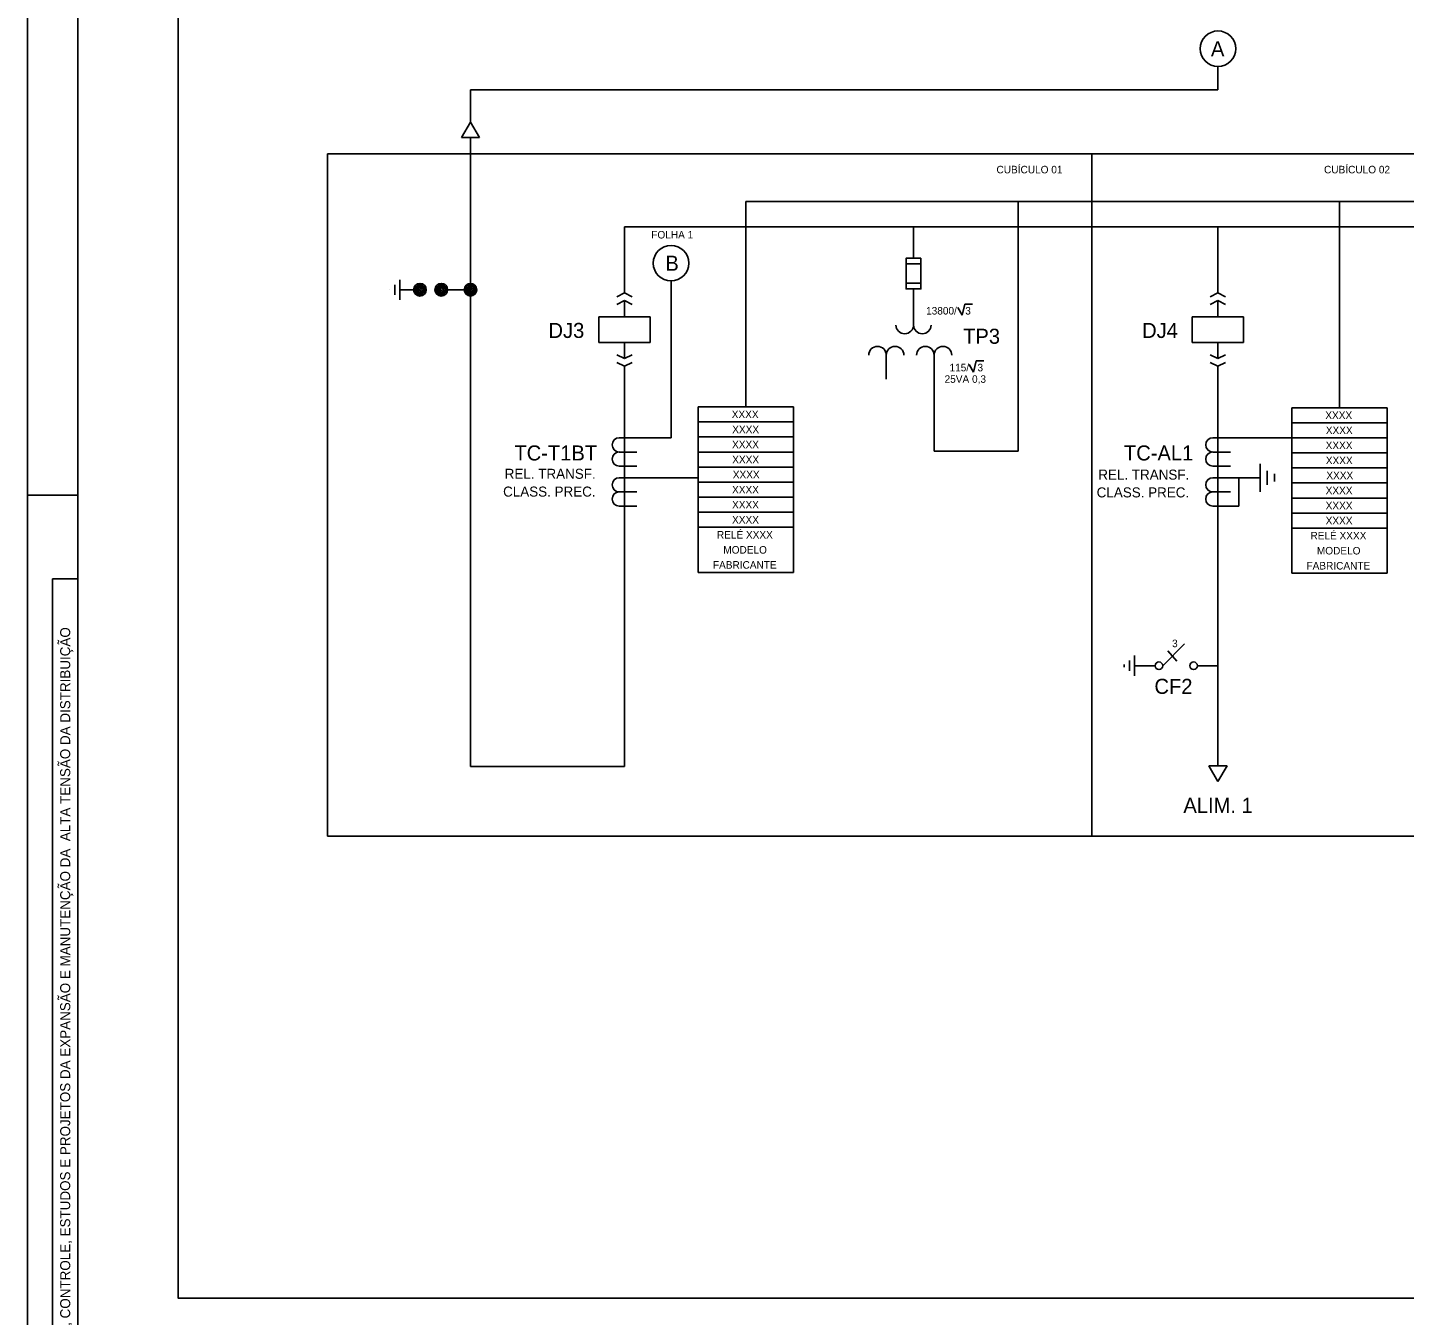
# Model space of a CAD drawing. Extents: x 563 to 1404, y 358 to 952.
# Drawn here: x 562.6 to 837, y 491.5 to 748.2 of the extents above; entities that cross this region are included whole.
import ezdxf

# ---------------------------------------------------------------- set-up
doc = ezdxf.new("R2010")
doc.units = 0
doc.layers.add('13', color=7, linetype='Continuous')
doc.layers.add('New Level (0)', color=7, linetype='Continuous')

# ---------------------------------------------------------------- blocks, each defined once
blk = doc.blocks.new('_U3')
for p, q in [((-1.47, 0.42), (-0.62, -1.12)), ((-0.62, -1.12), (-0.07, 1.12)), ((-0.07, 1.12), (1.47, 1.12))]:
    blk.add_line(p, q)

msp = doc.modelspace()

# ---------------------------------------------------------------- linework, layer by layer
for p, q in [((799.81, 740.38), (799.81, 735.75)), ((650.86, 729.31), (650.86, 735.75)), ((650.86, 735.75), (799.81, 735.75)), ((650.86, 729.31), (649.05, 726.21)), ((652.67, 726.21), (650.86, 729.31)), ((649.05, 726.21), (652.67, 726.21)), ((649.05, 726.21), (652.67, 726.21)), ((1296.89, 722.95), (622.37, 722.95)), ((622.37, 722.95), (622.37, 586.96)), ((774.67, 722.95), (774.67, 586.96)), ((774.67, 722.95), (774.67, 586.96)), ((1280.96, 713.45), (705.72, 713.45)), ((705.72, 672.55), (705.72, 713.45)), ((759.97, 663.73), (759.97, 713.45)), ((824.01, 672.38), (824.01, 713.45)), ((1256.75, 708.46), (681.52, 708.46)), ((681.52, 695.25), (681.52, 708.46)), ((739.14, 708.46), (739.14, 702.17)), ((799.81, 695.25), (799.81, 708.46)), ((799.81, 695.25), (799.81, 708.46)), ((740.6, 701.05), (737.67, 701.05)), ((636.77, 693.89), (636.77, 697.89)), ((690.82, 666.38), (690.82, 697.64)), ((740.6, 697.18), (737.67, 697.18)), ((634.77, 695.89), (634.77, 695.89)), ((635.77, 696.89), (635.77, 694.89)), ((640.77, 695.89), (636.77, 695.89)), ((640.77, 695.89), (636.77, 695.89)), ((650.86, 695.89), (646.27, 695.89)), ((739.14, 696.05), (739.14, 688.86)), ((681.52, 690.5), (681.52, 693.73)), ((681.52, 690.5), (681.52, 693.73)), ((799.81, 690.5), (799.81, 693.73)), ((799.81, 690.5), (799.81, 693.73)), ((676.4, 685.38), (676.4, 690.5)), ((676.4, 690.5), (686.64, 690.5)), ((686.64, 690.5), (686.64, 685.38)), ((794.69, 685.38), (794.69, 690.5)), ((794.69, 690.5), (804.93, 690.5)), ((804.93, 690.5), (804.93, 685.38)), ((686.64, 685.38), (676.4, 685.38)), ((681.52, 685.38), (681.52, 682.16)), ((804.93, 685.38), (794.69, 685.38)), ((799.81, 685.38), (799.81, 682.16)), ((681.52, 600.87), (681.52, 680.63)), ((733.71, 678.08), (733.71, 682.86)), ((743.25, 682.86), (743.25, 663.73)), ((799.81, 600.97), (799.81, 680.63)), ((715.21, 672.55), (696.23, 672.55)), ((696.23, 672.55), (696.23, 639.55)), ((715.21, 672.55), (715.21, 639.55)), ((833.5, 672.38), (814.52, 672.38)), ((814.52, 672.38), (814.52, 639.38)), ((833.5, 672.38), (833.5, 639.38)), ((715.21, 669.55), (696.23, 669.55)), ((833.5, 669.38), (814.52, 669.38)), ((680.5, 666.38), (684.03, 666.38)), ((690.82, 666.38), (684.03, 666.38)), ((715.21, 666.55), (696.23, 666.55)), ((798.79, 666.38), (802.32, 666.38)), ((814.52, 666.38), (802.32, 666.38)), ((833.5, 666.38), (814.52, 666.38)), ((680.5, 663.55), (684.03, 663.55)), ((715.21, 663.55), (696.23, 663.55)), ((759.97, 663.73), (743.25, 663.73)), ((798.79, 663.55), (802.32, 663.55)), ((833.5, 663.38), (814.52, 663.38)), ((680.5, 660.72), (684.03, 660.72)), ((715.21, 660.55), (696.23, 660.55)), ((798.79, 660.72), (802.32, 660.72)), ((808.19, 661.21), (808.19, 655.63)), ((809.59, 657.02), (809.59, 659.82)), ((811.07, 659.2), (811.07, 657.64)), ((833.5, 660.38), (814.52, 660.38)), ((680.5, 658.42), (684.03, 658.42)), ((696.23, 658.42), (684.03, 658.42)), ((715.21, 657.55), (696.23, 657.55)), ((798.79, 658.42), (802.32, 658.42)), ((799.81, 658.42), (808.19, 658.42)), ((833.5, 657.38), (814.52, 657.38)), ((680.5, 655.59), (684.03, 655.59)), ((715.21, 654.55), (696.23, 654.55)), ((715.21, 654.55), (696.23, 654.55)), ((798.79, 655.59), (802.32, 655.59)), ((833.5, 654.38), (814.52, 654.38)), ((833.5, 654.38), (814.52, 654.38)), ((680.5, 652.76), (684.03, 652.76)), ((715.21, 651.55), (696.23, 651.55)), ((798.79, 652.76), (804, 652.76)), ((833.5, 651.38), (814.52, 651.38)), ((715.21, 648.55), (696.23, 648.55)), ((833.5, 648.38), (814.52, 648.38)), ((715.21, 639.55), (696.23, 639.55)), ((833.5, 639.38), (814.52, 639.38)), ((783.18, 623), (783.18, 618.91)), ((793.15, 625.29), (788.81, 620.95)), ((789.8, 623.9), (791.6, 621.88)), ((781.14, 621.19), (781.14, 620.66)), ((782.15, 619.93), (782.15, 621.98)), ((787.27, 620.95), (783.18, 620.95)), ((799.81, 620.95), (795.71, 620.95)), ((801.62, 600.97), (798, 600.97)), ((798, 600.97), (799.81, 597.87)), ((801.62, 600.97), (798, 600.97)), ((799.81, 597.87), (801.62, 600.97)), ((1296.89, 586.96), (622.37, 586.96))]:
    msp.add_line(p, q)
msp.add_lwpolyline([(681.52, 600.87), (650.86, 600.87), (650.86, 726.21)])
msp.add_lwpolyline([(740.6, 702.17), (737.67, 702.17), (737.67, 696.05), (740.6, 696.05)], close=True)
for centre, radius in [((640.77, 695.89), 1.25), ((645.02, 695.89), 1.25), ((650.86, 695.89), 1.25), ((640.77, 695.89), 1), ((640.77, 695.89), 0.75), ((640.77, 695.89), 0.5), ((640.77, 695.89), 0.25), ((645.02, 695.89), 1), ((645.02, 695.89), 0.75), ((645.02, 695.89), 0.5), ((645.02, 695.89), 0.25), ((650.86, 695.89), 1), ((650.86, 695.89), 0.75), ((650.86, 695.89), 0.5), ((650.86, 695.89), 0.25), ((788.04, 620.95), 0.768), ((794.95, 620.95), 0.768)]:
    msp.add_circle(centre, radius)
for centre, radius, start, end in [((737.39, 688.86), 1.75, 180, 360), ((740.89, 688.86), 1.75, 180, 360), ((731.96, 682.86), 1.75, 0, 180), ((735.46, 682.86), 1.75, 0, 180), ((741.5, 682.86), 1.75, 0, 180), ((745, 682.86), 1.75, 0, 180), ((680.5, 664.97), 1.42, 90, 270), ((798.79, 664.97), 1.42, 90, 270), ((680.5, 662.14), 1.42, 90, 270), ((798.79, 662.14), 1.42, 90, 270), ((680.5, 657.01), 1.42, 90, 270), ((798.79, 657.01), 1.42, 90, 270), ((680.5, 654.18), 1.42, 90, 270), ((798.79, 654.18), 1.42, 90, 270)]:
    msp.add_arc(centre, radius, start, end)
at = {"layer": '13'}
for p, q in [((681.52, 695.25), (679.99, 694.49)), ((681.52, 695.25), (683.05, 694.49)), ((799.81, 695.25), (798.28, 694.49)), ((799.81, 695.25), (801.34, 694.49)), ((681.52, 693.73), (679.99, 692.97)), ((681.52, 693.73), (683.05, 692.97)), ((799.81, 693.73), (798.28, 692.97)), ((799.81, 693.73), (801.34, 692.97)), ((681.52, 682.16), (679.99, 682.92)), ((681.52, 680.63), (679.99, 681.4)), ((681.52, 682.16), (683.05, 682.92)), ((681.52, 680.63), (683.05, 681.4)), ((799.81, 682.16), (798.28, 682.92)), ((799.81, 680.63), (798.28, 681.4)), ((799.81, 682.16), (801.34, 682.92)), ((799.81, 680.63), (801.34, 681.4))]:
    msp.add_line(p, q, dxfattribs=at)
at = {"layer": 'New Level (0)'}
for p, q in [((562.58, 951.96), (562.58, 357.96)), ((562.58, 951.96), (562.58, 357.96)), ((572.58, 941.96), (572.58, 367.96)), ((572.58, 941.96), (572.58, 367.96)), ((804, 658.42), (804, 652.76)), ((562.58, 654.96), (572.58, 654.96)), ((567.58, 638.29), (572.58, 638.29)), ((567.58, 434.97), (567.58, 638.29))]:
    msp.add_line(p, q, dxfattribs=at)
msp.add_lwpolyline([(592.61, 760.21), (1379.09, 760.21), (1379.09, 494.89), (592.61, 494.89)], close=True, dxfattribs=at)
for centre in [(799.81, 743.93), (690.82, 701.18)]:
    msp.add_circle(centre, 3.54, dxfattribs=at)

# ---------------------------------------------------------------- block references
for p in [(749.45, 691.92), (751.68, 680.6)]:
    msp.add_blockref('_U3', p)

# ---------------------------------------------------------------- texts
for s, height, p in [('A', 3, (798.41, 742.43)), ('CUBÍCULO 01', 1.5, (755.67, 719.09)), ('CUBÍCULO 02', 1.5, (820.95, 719.09)), ('FOLHA 1', 1.5, (686.88, 706.11)), ('B', 3, (689.69, 699.68)), ('13800/   3', 1.5, (741.64, 690.95)), ('DJ3', 3, (666.39, 686.28)), ('DJ4', 3, (784.69, 686.28)), ('TP3', 3, (749.02, 685.12)), ('115/   3', 1.5, (746.31, 679.63)), ('25VA 0,3', 1.5, (745.33, 677.34)), ('XXXX', 1.5, (702.91, 670.3)), ('XXXX', 1.5, (821.2, 670.13)), ('XXXX', 1.5, (703.01, 667.3)), ('XXXX', 1.5, (821.3, 667.13)), ('TC-T1BT', 3, (659.6, 661.86)), ('XXXX', 1.5, (702.98, 664.3)), ('TC-AL1', 3, (781.07, 661.86)), ('XXXX', 1.5, (821.27, 664.13)), ('XXXX', 1.5, (703.01, 661.3)), ('XXXX', 1.5, (821.3, 661.13)), ('REL. TRANSF.', 2, (657.67, 658.21)), ('XXXX', 1.5, (703.12, 658.3)), ('REL. TRANSF.', 2, (775.96, 658.04)), ('XXXX', 1.5, (821.41, 658.13)), ('CLASS. PREC.', 2, (657.35, 654.66)), ('XXXX', 1.5, (702.98, 655.3)), ('CLASS. PREC.', 2, (775.64, 654.5)), ('XXXX', 1.5, (821.27, 655.13)), ('XXXX', 1.5, (702.98, 652.3)), ('XXXX', 1.5, (821.27, 652.13)), ('XXXX', 1.5, (702.98, 649.3)), ('XXXX', 1.5, (821.27, 649.13)), ('RELÉ XXXX', 1.5, (699.95, 646.3)), ('RELÉ XXXX', 1.5, (818.24, 646.13)), ('MODELO', 1.5, (701.23, 643.3)), ('MODELO', 1.5, (819.52, 643.13)), ('FABRICANTE', 1.5, (699.16, 640.3)), ('FABRICANTE', 1.5, (817.45, 640.13)), ('3', 1.5, (790.66, 624.65)), ('CF2', 3, (787.15, 615.34)), ('ALIM. 1', 3, (792.92, 591.63))]:
    msp.add_text(s, height=height).set_placement(p)
msp.add_text('EA/EA - GERÊNCIA DE DE ESTRATÉGIA, CONTROLE, ESTUDOS E PROJETOS DA EXPANSÃO E MANUTENÇÃO DA  ALTA TENSÃO DA DISTRIBUIÇÃO', height=2, rotation=90, dxfattribs=at).set_placement((571.08, 438.56))

doc.saveas('drawing.dxf')
